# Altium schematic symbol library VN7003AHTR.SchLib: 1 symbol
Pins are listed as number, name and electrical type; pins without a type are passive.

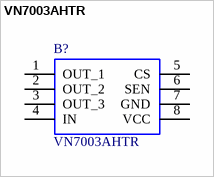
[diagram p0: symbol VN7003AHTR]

## VN7003AHTR
designator B?
Gate Drivers ABD VIPOWER; Manufacturer_Name: STMicroelectronics
footprint OCTAPAK
pins: 1 OUT_1, 2 OUT_2, 3 OUT_3, 4 IN, 5 CS, 6 SEN, 7 GND, 8 VCC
